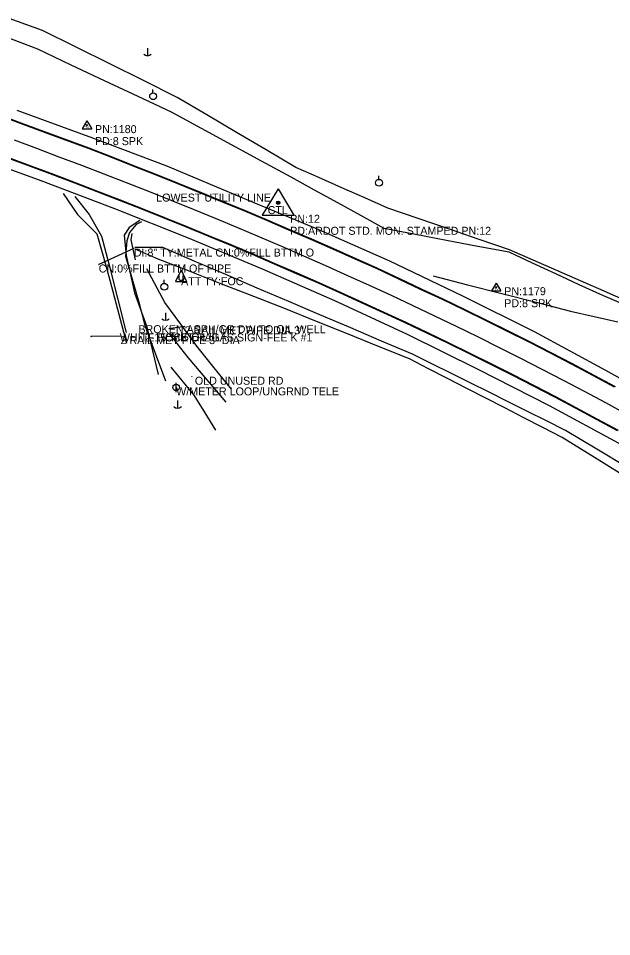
# Model space of a CAD drawing. Extents: x 878399 to 889864, y 1564003 to 1567413.
# Drawn here: x 882722 to 883093, y 1566499 to 1567072 of the extents above; entities that cross this region are included whole.
import ezdxf

# ---------------------------------------------------------------- set-up
doc = ezdxf.new("R2010")
doc.units = 0
for name, color, linetype in [('S_DITCHLINE', 7, 'Continuous'), ('S_DRG_PT_SYM', 7, 'Continuous'), ('S_DRIVEWAY', 7, 'Continuous'), ('S_EDGE_PAVEMENT', 7, 'Continuous'), ('S_ELECTRIC_UTILITIES_ANNOT', 7, 'Continuous'), ('S_FENCE', 7, 'Continuous'), ('S_FENCE_ANNOT', 7, 'Continuous'), ('S_GATE_ANNOT', 7, 'Continuous'), ('S_GRAVEL_ROAD', 7, 'Continuous'), ('S_HEADWALL', 7, 'Continuous'), ('S_MSC_PT_SYM', 7, 'Continuous'), ('S_PAVEMENT_CROWN', 7, 'Continuous'), ('S_PRIMARY_CTL', 7, 'Continuous'), ('S_PRIMARY_CTL_ANNOT', 7, 'Continuous'), ('S_SECONDARY_CTL', 7, 'Continuous'), ('S_SECONDARY_CTL_ANNOT', 7, 'Continuous'), ('S_SHOULDER', 7, 'Continuous'), ('S_SIDE_DRAIN', 7, 'Continuous'), ('S_SIDE_DRAIN_ANNOT', 7, 'Continuous'), ('S_SURVEY_TEXT_ANNOT', 7, 'Continuous'), ('S_TRAILS', 7, 'Continuous'), ('S_UTILITY_POLE', 7, 'Continuous'), ('S_UTILITY_POLE_ANNOT', 7, 'Continuous'), ('S_UTL_PT_SYM', 7, 'Continuous')]:
    doc.layers.add(name, color=color, linetype=linetype)

msp = doc.modelspace()

# ---------------------------------------------------------------- linework, layer by layer
at = {"layer": 'S_DITCHLINE'}
for points in [[(883109.57, 1566892.3), (883088.24, 1566901.73), (883073.47, 1566908.18), (883058.69, 1566914.64), (883043.92, 1566921.09), (883029.15, 1566927.55), (883010.12, 1566934.07), (882991.09, 1566940.59), (882972.06, 1566947.12), (882953.03, 1566953.64), (882938.68, 1566959.98), (882924.33, 1566966.33), (882909.98, 1566972.67), (882895.63, 1566979.02), (882877.09, 1566989.95), (882858.55, 1567000.89), (882840, 1567011.82), (882821.46, 1567022.76), (882800.41, 1567033.23), (882779.36, 1567043.7), (882758.31, 1567054.17), (882737.26, 1567064.64), (882716.39, 1567072.13)], [(883108.89, 1566889.75), (883087.43, 1566898.94), (883072.79, 1566905.7), (883058.15, 1566912.46), (883043.51, 1566919.22), (883028.87, 1566925.98), (883009.36, 1566929.71), (882989.85, 1566933.44), (882970.33, 1566937.17), (882950.82, 1566940.89), (882936.31, 1566948.89), (882921.81, 1566956.89), (882907.3, 1566964.88), (882892.8, 1566972.88), (882874.07, 1566983.02), (882855.34, 1566993.16), (882836.61, 1567003.31), (882817.88, 1567013.45), (882796.99, 1567023.29), (882776.1, 1567033.14), (882755.22, 1567042.98), (882734.33, 1567052.82), (882713.46, 1567060.86)], [(883103.11, 1566791.36), (883083.69, 1566803.06), (883064.27, 1566814.75), (883052.31, 1566820.7), (883040.36, 1566826.65), (883028.4, 1566832.6), (883016.44, 1566838.55), (883004.49, 1566844.5), (882992.53, 1566850.45), (882980.58, 1566856.4), (882968.62, 1566862.35), (882949.26, 1566870.56), (882929.9, 1566878.77), (882910.53, 1566886.97), (882891.17, 1566895.18), (882871.48, 1566903.64), (882851.79, 1566912.1), (882832.1, 1566920.56), (882812.41, 1566929.01), (882795.03, 1566929.05)], [(883099.36, 1566787.24), (883080.68, 1566798.82), (883062, 1566810.41), (883050.08, 1566816.53), (883038.16, 1566822.65), (883026.24, 1566828.77), (883014.32, 1566834.89), (883002.4, 1566841.01), (882990.49, 1566847.13), (882978.57, 1566853.25), (882966.65, 1566859.37), (882947.29, 1566867.2), (882927.94, 1566875.02), (882908.58, 1566882.85), (882889.23, 1566890.67), (882869.32, 1566898.43), (882849.42, 1566906.19), (882829.51, 1566913.95), (882809.61, 1566921.71), (882795.27, 1566927.9)], [(882855.45, 1566840.47), (882844.57, 1566853.89), (882833.69, 1566867.3), (882823.73, 1566881.01), (882813.78, 1566894.71), (882802.46, 1566915.59)]]:
    msp.add_lwpolyline(points, dxfattribs=at)
at = {"layer": 'S_DRG_PT_SYM'}
for points in [[(882794.31, 1566928.35), (882794.31, 1566928.4), (882794.31, 1566928.35), (882794.26, 1566928.35), (882794.31, 1566928.35), (882794.31, 1566928.3), (882794.31, 1566928.35), (882794.36, 1566928.35)], [(882772.41, 1566918.38), (882772.41, 1566918.43), (882772.41, 1566918.38), (882772.36, 1566918.38), (882772.41, 1566918.38), (882772.41, 1566918.33), (882772.41, 1566918.38), (882772.46, 1566918.38)]]:
    msp.add_lwpolyline(points, dxfattribs=at)
at = {"layer": 'S_DRIVEWAY'}
for points in [[(882750.15, 1566962.66), (882759.2, 1566949.64), (882771.22, 1566937.47), (882775.33, 1566923.04), (882779.44, 1566908.62), (882789.76, 1566869.15)], [(882757.54, 1566960.92), (882766.42, 1566949.65), (882774.17, 1566936.15), (882778.65, 1566918.7), (882784.07, 1566897.29), (882789.49, 1566875.89)], [(882798.08, 1566945.89), (882791.46, 1566941.54), (882788.36, 1566936.67), (882789.59, 1566923.9), (882794.72, 1566900.66), (882802.41, 1566879.36), (882805.95, 1566864.5), (882809.49, 1566849.65)], [(882799.24, 1566945.12), (882795.87, 1566943.32), (882791.69, 1566938.33), (882789.96, 1566933.25), (882789.24, 1566923.64), (882793.3, 1566909.2), (882797.42, 1566894.78), (882801.26, 1566880.27), (882814.21, 1566845.63)]]:
    msp.add_lwpolyline(points, dxfattribs=at)
at = {"layer": 'S_EDGE_PAVEMENT'}
for points in [[(882709.18, 1567011.82), (882723.31, 1567006.76), (882737.37, 1567001.54), (882751.44, 1566996.33), (882765.78, 1566991.01), (882779.74, 1566985.54), (882793.71, 1566980.07), (882807.68, 1566974.6), (882807.68, 1566974.6), (882821.6, 1566969.01), (882821.6, 1566969.01), (882835.5, 1566963.36), (882835.5, 1566963.36), (882849.62, 1566957.62), (882849.62, 1566957.62), (882863.48, 1566951.89), (882863.48, 1566951.89), (882877.28, 1566946.01), (882891.08, 1566940.12), (882904.88, 1566934.24), (882918.58, 1566928.13), (882918.58, 1566928.13), (882932.55, 1566921.9), (882946.24, 1566915.78), (882959.86, 1566909.48), (882973.42, 1566903.07), (882986.98, 1566896.66), (883000.84, 1566890.02), (883014.29, 1566883.38), (883014.29, 1566883.38), (883027.74, 1566876.74), (883041.19, 1566870.1), (883041.19, 1566870.1), (883054.49, 1566863.16), (883067.79, 1566856.23), (883067.79, 1566856.23), (883081.47, 1566849.09), (883094.67, 1566841.96)], [(882709.71, 1567012.02), (882723.83, 1567006.96), (882737.89, 1567001.75), (882751.96, 1566996.53), (882766.29, 1566991.22), (882780.26, 1566985.75), (882794.23, 1566980.27), (882808.19, 1566974.8), (882808.19, 1566974.8), (882822.12, 1566969.21), (882822.12, 1566969.21), (882836.01, 1566963.56), (882836.01, 1566963.56), (882850.13, 1566957.82), (882850.13, 1566957.82), (882864, 1566952.1), (882864, 1566952.1), (882877.79, 1566946.21), (882891.59, 1566940.33), (882905.39, 1566934.45), (882919.09, 1566928.34), (882919.09, 1566928.34), (882933.06, 1566922.1), (882946.75, 1566915.99), (882960.36, 1566909.69), (882973.93, 1566903.28), (882987.49, 1566896.87), (883001.35, 1566890.23), (883014.8, 1566883.59), (883014.8, 1566883.59), (883028.25, 1566876.95), (883041.7, 1566870.31), (883041.7, 1566870.31), (883055, 1566863.37), (883068.3, 1566856.44), (883068.3, 1566856.44), (883081.97, 1566849.3), (883095.17, 1566842.17)], [(882715.39, 1566984.97), (882729.49, 1566979.85), (882743.56, 1566974.63), (882757.2, 1566969.38), (882771.2, 1566963.99), (882785.2, 1566958.6), (882799.14, 1566953.06), (882813.08, 1566947.51), (882827.02, 1566941.97), (882840.59, 1566936.36), (882854.42, 1566930.57), (882868.26, 1566924.77), (882882.06, 1566918.89), (882882.06, 1566918.89), (882895.8, 1566912.86), (882909.53, 1566906.83), (882922.91, 1566900.94), (882936.55, 1566894.7), (882950.19, 1566888.46), (882963.83, 1566882.22), (882977.36, 1566875.75), (882977.36, 1566875.75), (882990.4, 1566869.42), (883003.9, 1566862.87), (883017.34, 1566856.21), (883030.69, 1566849.37), (883044.04, 1566842.53), (883057.39, 1566835.69), (883070.11, 1566828.87), (883083.33, 1566821.79), (883096.56, 1566814.71)], [(882715.92, 1566985.18), (882730.02, 1566980.06), (882744.08, 1566974.84), (882757.72, 1566969.59), (882771.72, 1566964.2), (882785.72, 1566958.81), (882799.65, 1566953.26), (882813.59, 1566947.72), (882827.53, 1566942.18), (882841.1, 1566936.57), (882854.94, 1566930.78), (882868.77, 1566924.98), (882882.57, 1566919.1), (882882.57, 1566919.1), (882896.31, 1566913.07), (882910.04, 1566907.04), (882923.42, 1566901.15), (882937.06, 1566894.91), (882950.7, 1566888.67), (882964.34, 1566882.43), (882977.87, 1566875.96), (882977.87, 1566875.96), (882990.91, 1566869.63), (883004.41, 1566863.08), (883017.85, 1566856.42), (883031.2, 1566849.58), (883044.55, 1566842.75), (883057.89, 1566835.9), (883070.61, 1566829.09), (883083.84, 1566822), (883097.06, 1566814.92)]]:
    msp.add_lwpolyline(points, dxfattribs=at)
at = {"layer": 'S_FENCE'}
for p, q in [((882826.12, 1566879.74), (882816.28, 1566878.14)), ((882786.03, 1566873.65), (882767.61, 1566873.3))]:
    msp.add_line(p, q, dxfattribs=at)
at = {"layer": 'S_GRAVEL_ROAD'}
msp.add_lwpolyline([(882981.42, 1566911.28), (883002.89, 1566905.77), (883024.37, 1566900.26), (883045.84, 1566894.75), (883067.31, 1566889.24), (883082.12, 1566885.93), (883096.93, 1566882.62)], dxfattribs=at)
at = {"layer": 'S_HEADWALL'}
msp.add_lwpolyline([(882793.14, 1566937.69), (882792.42, 1566933.69), (882795.16, 1566921.37)], dxfattribs=at)
at = {"layer": 'S_MSC_PT_SYM'}
for points in [[(882797.22, 1566880.47), (882797.22, 1566880.52), (882797.22, 1566880.47), (882797.17, 1566880.47), (882797.22, 1566880.47), (882797.22, 1566880.42), (882797.22, 1566880.47), (882797.27, 1566880.47)], [(882816.28, 1566878.14), (882816.28, 1566878.19), (882816.28, 1566878.14), (882816.23, 1566878.14), (882816.28, 1566878.14), (882816.28, 1566878.09), (882816.28, 1566878.14), (882816.33, 1566878.14)], [(882826.12, 1566879.74), (882826.12, 1566879.79), (882826.12, 1566879.74), (882826.07, 1566879.74), (882826.12, 1566879.74), (882826.12, 1566879.69), (882826.12, 1566879.74), (882826.17, 1566879.74)], [(882767.61, 1566873.3), (882767.61, 1566873.35), (882767.61, 1566873.3), (882767.56, 1566873.3), (882767.61, 1566873.3), (882767.61, 1566873.25), (882767.61, 1566873.3), (882767.66, 1566873.3)], [(882785.63, 1566875.32), (882785.63, 1566875.37), (882785.63, 1566875.32), (882785.58, 1566875.32), (882785.63, 1566875.32), (882785.63, 1566875.27), (882785.63, 1566875.32), (882785.68, 1566875.32)], [(882786.03, 1566873.65), (882786.03, 1566873.7), (882786.03, 1566873.65), (882785.98, 1566873.65), (882786.03, 1566873.65), (882786.03, 1566873.6), (882786.03, 1566873.65), (882786.08, 1566873.65)], [(882801.23, 1566875.32), (882801.23, 1566875.37), (882801.23, 1566875.32), (882801.18, 1566875.32), (882801.23, 1566875.32), (882801.23, 1566875.27), (882801.23, 1566875.32), (882801.28, 1566875.32)], [(882830.66, 1566848.27), (882830.66, 1566848.32), (882830.66, 1566848.27), (882830.61, 1566848.27), (882830.66, 1566848.27), (882830.66, 1566848.22), (882830.66, 1566848.27), (882830.71, 1566848.27)]]:
    msp.add_lwpolyline(points, dxfattribs=at)
at = {"layer": 'S_PAVEMENT_CROWN'}
msp.add_lwpolyline([(882719.46, 1566996.18), (882733.53, 1566990.96), (882747.58, 1566985.71), (882761.6, 1566980.48), (882775.6, 1566975.1), (882789.56, 1566969.6), (882803.51, 1566964.1), (882817.46, 1566958.56), (882831.34, 1566952.88), (882845.2, 1566947.22), (882845.2, 1566947.22), (882845.2, 1566947.22), (882859.08, 1566941.54), (882872.88, 1566935.66), (882886.67, 1566929.74), (882900.45, 1566923.82), (882914.18, 1566917.77), (882927.81, 1566911.61), (882941.48, 1566905.44), (882941.48, 1566905.44), (882955.13, 1566899.22), (882968.69, 1566892.79), (882982.24, 1566886.36), (882995.74, 1566879.96), (883009.19, 1566873.31), (883009.19, 1566873.31), (883022.61, 1566866.61), (883036.03, 1566859.92), (883049.39, 1566853.08), (883062.67, 1566846.11), (883075.89, 1566839.17), (883089.15, 1566832.14), (883102.25, 1566824.84)], dxfattribs=at)
at = {"layer": 'S_PRIMARY_CTL'}
for p, q in [((882884.57, 1566965.63), (882874.54, 1566949.11)), ((882884.57, 1566965.63), (882894.39, 1566949.11)), ((882874.54, 1566949.11), (882894.39, 1566949.11))]:
    msp.add_line(p, q, dxfattribs=at)
for radius in [1.04, 0.609, 0.344]:
    msp.add_circle((882884.57, 1566956.93), radius, dxfattribs=at)
at = {"layer": 'S_SECONDARY_CTL'}
for p, q in [((882765.06, 1567008.06), (882762.05, 1567003.11)), ((882765.06, 1567008.06), (882768.01, 1567003.11)), ((882762.05, 1567003.11), (882768.01, 1567003.11)), ((883020.86, 1566906.82), (883017.85, 1566901.87)), ((883020.86, 1566906.82), (883023.81, 1566901.87)), ((883017.85, 1566901.87), (883023.81, 1566901.87))]:
    msp.add_line(p, q, dxfattribs=at)
for centre, radius in [((882765.06, 1567005.45), 0.311), ((882765.06, 1567005.45), 0.183), ((882765.06, 1567005.45), 0.103), ((883020.86, 1566904.21), 0.311), ((883020.86, 1566904.21), 0.183), ((883020.86, 1566904.21), 0.103)]:
    msp.add_circle(centre, radius, dxfattribs=at)
at = {"layer": 'S_SHOULDER'}
for points in [[(882721.15, 1567014.88), (882768.55, 1566997.45), (882815.33, 1566979.79), (882861.85, 1566960.33), (882907.96, 1566940.99), (882954.18, 1566920.59), (882999.89, 1566898.78), (883044.63, 1566876.45), (883089.22, 1566852.28), (883132.94, 1566828.01), (883176.41, 1566802.24), (883219.06, 1566776.13), (883261.55, 1566749.01), (883303.5, 1566721.79), (883345.59, 1566694), (883386.9, 1566665.83), (883428.02, 1566636.53), (883468.74, 1566606.41), (883508.31, 1566575.84), (883547.66, 1566544.44)], [(882689.13, 1566987.9), (882736.13, 1566970.85), (882782.37, 1566953.35), (882828.37, 1566934.96), (882874.53, 1566915.73), (882919.81, 1566895.88), (882965.22, 1566874.95), (883009.35, 1566853.05), (883053.86, 1566830.25), (883097.13, 1566806.93), (883139.92, 1566782.33), (883182.72, 1566756.47), (883224.64, 1566730.13), (883266.67, 1566703.05), (883307.99, 1566675.86), (883349.44, 1566647.89), (883390.09, 1566619.76), (883430.54, 1566590.36), (883469.72, 1566560.5), (883509.1, 1566529.69), (883547.7, 1566498.51)]]:
    msp.add_lwpolyline(points, dxfattribs=at)
at = {"layer": 'S_SIDE_DRAIN'}
msp.add_line((882794.31, 1566928.35), (882772.41, 1566918.38), dxfattribs=at)
at = {"layer": 'S_TRAILS'}
for points in [[(882851.98, 1566832.46), (882840.17, 1566846.39), (882828.36, 1566860.33), (882816.87, 1566874.89)], [(882817.57, 1566854.3), (882831.87, 1566836.72), (882838.66, 1566825.77), (882845.45, 1566814.81)]]:
    msp.add_lwpolyline(points, dxfattribs=at)
at = {"layer": 'S_UTILITY_POLE'}
for p, q in [((882802.86, 1567053.54), (882802.86, 1567048.81)), ((882806.28, 1567025.64), (882806.28, 1567027.75)), ((882947.51, 1566971.59), (882947.51, 1566973.7)), ((882823.89, 1566914.95), (882820.37, 1566907.86)), ((882823.89, 1566914.95), (882827.38, 1566907.86)), ((882813.28, 1566906.62), (882813.28, 1566908.72)), ((882820.37, 1566907.86), (882827.38, 1566907.86)), ((882822.69, 1566909.1), (882822.69, 1566911.54)), ((882823.31, 1566908.44), (882822.69, 1566909.1)), ((882824.51, 1566908.44), (882823.31, 1566908.44)), ((882825.06, 1566909.1), (882824.51, 1566908.44)), ((882825.06, 1566911.54), (882825.06, 1566909.1)), ((882814.09, 1566888.27), (882814.09, 1566883.54)), ((882820.81, 1566838.69), (882820.81, 1566844.48)), ((882821.65, 1566833.37), (882821.65, 1566828.64))]:
    msp.add_line(p, q, dxfattribs=at)
for centre, radius in [((882806.4, 1567023.5), 2.13), ((882947.63, 1566969.45), 2.13), ((882813.4, 1566904.47), 2.13), ((882820.81, 1566841.62), 2.05)]:
    msp.add_circle(centre, radius, dxfattribs=at)
for centre in [(882802.92, 1567052.24), (882814.16, 1566886.96), (882821.71, 1566832.06)]:
    msp.add_arc(centre, 3.41, 226.39718, 313.60282, dxfattribs=at)
at = {"layer": 'S_UTL_PT_SYM'}
msp.add_lwpolyline([(882808.34, 1566962.68), (882808.34, 1566962.73), (882808.34, 1566962.68), (882808.29, 1566962.68), (882808.34, 1566962.68), (882808.34, 1566962.63), (882808.34, 1566962.68), (882808.39, 1566962.68)], dxfattribs=at)

# ---------------------------------------------------------------- texts
at = {"layer": 'S_ELECTRIC_UTILITIES_ANNOT'}
msp.add_text('LOWEST UTILITY LINE', height=5, dxfattribs=at).set_placement((882808.34, 1566957.68))
at = {"layer": 'S_FENCE_ANNOT'}
for s, p in [('2 RAIL MET PIPE DIA 3"', (882826.12, 1566874.74)), ('2 RAIL MET PIPE 3" DIA', (882786.03, 1566868.65))]:
    msp.add_text(s, height=5, dxfattribs=at).set_placement(p)
at = {"layer": 'S_GATE_ANNOT'}
msp.add_text("2-15' MET RAIL", height=5, dxfattribs=at).set_placement((882801.23, 1566870.32))
at = {"layer": 'S_PRIMARY_CTL'}
msp.add_text('CTL', height=5, rotation=360, dxfattribs=at).set_placement((882877.98, 1566949.85))
at = {"layer": 'S_PRIMARY_CTL_ANNOT'}
for s, p in [('PN:12', (882892.07, 1566944.43)), ('PD:ARDOT STD. MON. STAMPED PN:12', (882892.07, 1566936.93))]:
    msp.add_text(s, height=5, dxfattribs=at).set_placement(p)
at = {"layer": 'S_SECONDARY_CTL'}
for p in [(882763.86, 1567003.44), (883019.66, 1566902.2)]:
    msp.add_text('TV', height=1.5, rotation=360, dxfattribs=at).set_placement(p)
at = {"layer": 'S_SECONDARY_CTL_ANNOT'}
for s, p in [('PN:1180', (882770.06, 1567000.45)), ('PD:8 SPK', (882770.06, 1566992.95)), ('PN:1179', (883025.86, 1566899.21)), ('PD:8 SPK', (883025.86, 1566891.71))]:
    msp.add_text(s, height=5, dxfattribs=at).set_placement(p)
at = {"layer": 'S_SIDE_DRAIN_ANNOT'}
for s, p in [('DI:8" TY:METAL CN:0%FILL BTTM O', (882794.31, 1566923.35)), ('CN:0%FILL BTTM OF PIPE', (882772.41, 1566913.38))]:
    msp.add_text(s, height=5, dxfattribs=at).set_placement(p)
at = {"layer": 'S_SURVEY_TEXT_ANNOT'}
for s, p in [('BROKEN ASPH/GR DW TO OIL WELL', (882797.22, 1566875.47)), ('WHITE ROCK OIL/GAS SIGN-FEE K #1', (882785.63, 1566870.32)), (' OLD UNUSED RD', (882830.66, 1566843.27))]:
    msp.add_text(s, height=5, dxfattribs=at).set_placement(p)
at = {"layer": 'S_UTILITY_POLE_ANNOT'}
for s, p in [('ATT TY:FOC', (882823.89, 1566905.42)), ('W/METER LOOP/UNGRND TELE', (882820.81, 1566836.62))]:
    msp.add_text(s, height=5, dxfattribs=at).set_placement(p)

doc.saveas('drawing.dxf')
